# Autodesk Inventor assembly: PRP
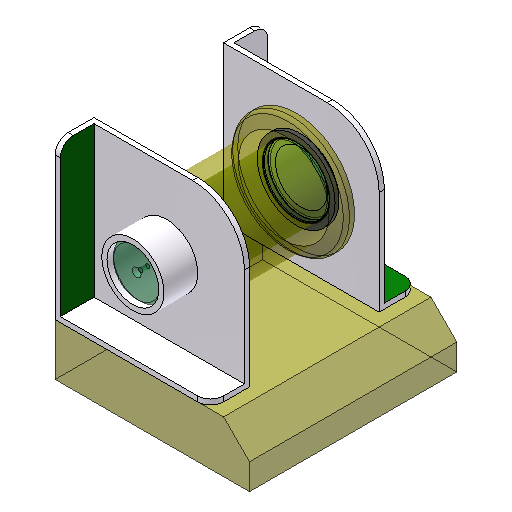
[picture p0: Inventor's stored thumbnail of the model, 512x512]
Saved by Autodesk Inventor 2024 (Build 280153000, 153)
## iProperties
Company: ATC
Created: 2023-03
Part Number: PRP
Document SubType Name: Assembly
Designer: Andrzej Jaskulski
Mass: 1986.93 g
Surface Area: 612.19 cm^2
Volume: 198.693 cm^3
Density: 10 g/cm^3
Stock Number: PRP
Checked By: A.J.
Engr Approved By: Andrzej Jaskulski
Mfg Approved By: Andrzej Jaskulski
Authority: A.J.
Title: A.J.: Kurs R2024-MEP
Author: Andrzej Jaskulski
Revision Number: 1/24
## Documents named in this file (4)
- C:\Users\AndJas\Documents\R2024-MEP\Obszar roboczy\PRP.iam
- C:\Users\AndJas\Documents\R2024-MEP\Obszar roboczy\PRP-Podstawa.ipt
- C:\Users\AndJas\Documents\R2024-MEP\Obszar roboczy\PRP-Podpora.ipt
- C:\Users\AndJas\Documents\R2024-MEP\Obszar roboczy\PRP-Zespół rolki.iam
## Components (4 placed, 3 different names)
1. PRP-Podstawa:1 — Zestawiający:1, Zestawiający:2, Zestawiający:3, Zestawiający:4
2. PRP-Podpora:1 — Zestawiający:1, Zestawiający:3, Wstaw:1
3. PRP-Podpora:2 — Zestawiający:2, Zestawiający:4
4. PRP-Zespół rolki:1 [sub-assembly] — Wstaw:1
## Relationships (5: Mate 4, Insert 1)
- Zestawiający:1 [Mate]: PRP-Podstawa:1 ↔ PRP-Podpora:1
- Zestawiający:2 [Mate]: PRP-Podstawa:1 ↔ PRP-Podpora:2
- Zestawiający:3 [Mate]: PRP-Podstawa:1 ↔ PRP-Podpora:1
- Zestawiający:4 [Mate]: PRP-Podstawa:1 ↔ PRP-Podpora:2
- Wstaw:1 [Insert]: PRP-Podpora:1 ↔ PRP-Zespół rolki:1
